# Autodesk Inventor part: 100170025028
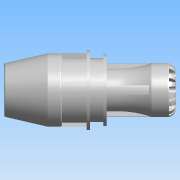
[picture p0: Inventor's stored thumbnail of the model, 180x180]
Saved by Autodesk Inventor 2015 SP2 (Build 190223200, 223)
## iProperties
Created: 2016-12
Part Number: 100170025028
Material: PVC-Piping
Description: PLASSON UNIVERSAL COUPLING 24-28X25 SERIES 1
Document SubType Name: Modeling
Designer: KIM
Density: 1.4 g/cm^3
Appearance: Smooth - White
Author: KIM
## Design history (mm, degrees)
derived "10017.ipt"
feature "Solid1::10017.ipt"
tag "TaggingFeature1"
body "Solid1"
other parameters: "d15" = 28, "d16" = 27.44, "d20" = 54.12, "d21" = 80 deg, "d22" = 20.28571, "d23" = 0, "d25" = 360 deg, "d48" = 1.25, "d52" = 0.66, "d72" = 25, "d73" = 48, "d74" = 2.5, "d79" = 31.25, "d80" = 20.16, "d81" = 77 deg, "d82" = 142, "d83" = 71, "d84" = 55, "d85" = 3.2, "d86" = 66, "d87" = 60.72, "d88" = 45, "d89" = 11, "d90" = 52.8, "d91" = 36, "d93" = 1.42, "d96" = 5.5, "d97" = 5.5, "d98" = 0, "d100" = 360 deg, "d103" = 0.5, "d104" = 0.5, "d105" = 8 deg, "d106" = 8 deg, "d108" = 0, "d110" = 360 deg, "d112" = 7.5, "d113" = 3.75, "d115" = 38.4, "d116" = 0, "d118" = 360 deg, "d120" = 6.6, "d121" = 0.66, "d_" = 25, "E_" = 66, "H_" = 142, "l_" = 48, "d_1" = 28, "l_1" = 55, "d66" = 76, "d68" = 41, "d69" = 45, "d70" = 20.955, "d71" = 13, "d92" = 6.875, "d94" = 45, "d102" = 31.25
